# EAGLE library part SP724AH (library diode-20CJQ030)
SP724 SCR Diode Array for ESD and Transient Overvoltage Protection Description: The SP724 is a quad array of transient voltage clamping circuits designed to suppress ESD and other transient over-voltage events. The SP724 is used to help protect sensitive digital or analog input circuits on data, signal, or control lines operating on power supplies up to 20VDC. The SP724 is comprised of bipolar SCR/diode structures to protect up to four independent lines by clamping transients of either polarity to the power supply rails. The SP724 offers very low leakage (1nA Typical) and low input capacitance (3pF Typical). Additionally, the SP724 is rated to withstand the IEC 61000-4-2 ESD specification for both contact and air discharge methods to level 4. The SP724 is connected to the sensitive input line and its associated power supply lines. Clamping action occurs during the transient pulse, turning on the diode and fast triggering SCR structures when the voltage on the input line exceeds one VBE threshold above the V+ supply (or one VBE threshold below the V- supply). Therefore, the SP724 operation is unaffected by poor power supply regulation or voltage fluctuations within its operating range. Features: An Array of 4 SCR/Diode Pairs in 6-Lead SOT-23 ESD Capability per HBM Standards - IEC 61000-4-2, Direct Discharge . . . . . . . . . . . . . . . . 8kV (Level 4) - IEC 61000-4-2, Air Discharge . . . . . . . . . . . . . . . . . 15kV (Level 4) - MIL STD 3015.7. . . . . . . . . . . . . . .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
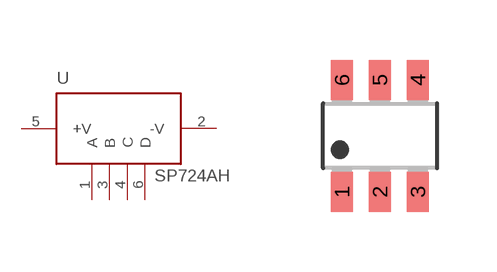
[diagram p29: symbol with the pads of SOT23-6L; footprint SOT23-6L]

Designator prefix U

## SP724AH  [SOT23-6L]
1  A
2  -V  pwr
3  B
4  C
5  +V  pwr
6  D

## Footprint SOT23-6L (pad centres in mm)
Small Outline Transistor
smd 0.55 x 1: 1 -0.95,-1.4; 2 0,-1.4; 3 0.95,-1.4; 4 0.95,1.4; 5 0,1.4; 6 -0.95,1.4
